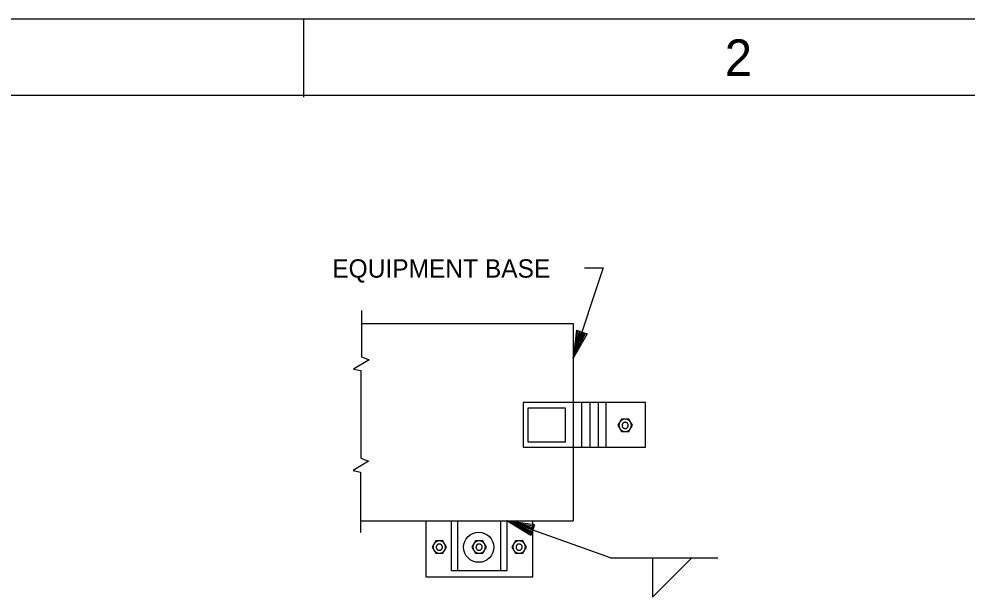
# Model space of a CAD drawing. Extents: x 9999.96 to 10005.26, y 9999.88 to 10002.38.
# Drawn here: x 10002.153 to 10002.67, y 10002.069 to 10002.385 of the extents above; entities that cross this region are included whole.
import ezdxf

# ---------------------------------------------------------------- set-up
doc = ezdxf.new("R2010")
doc.units = 0
doc.layers.add('Level 1', color=7, linetype='Continuous')
doc.layers.add('Level 2', color=7, linetype='Continuous')

msp = doc.modelspace()

# ---------------------------------------------------------------- linework, layer by layer
at = {"layer": 'Level 1'}
for p, q in [((9999.96033, 10002.38453), (10003.46033, 10002.38453)), ((10002.30795, 10002.38453), (10002.30795, 10002.34186)), ((10000.127, 10002.34286), (10003.41867, 10002.34286))]:
    msp.add_line(p, q, dxfattribs=at)
at = {"layer": 'Level 2'}
for p, q in [((10002.33947, 10002.21838), (10002.45502, 10002.21838)), ((10002.45502, 10002.21838), (10002.45502, 10002.17513)), ((10002.45681, 10002.21463), (10002.45491, 10002.1994)), ((10002.45491, 10002.1994), (10002.45754, 10002.21439)), ((10002.45491, 10002.1994), (10002.45835, 10002.21414)), ((10002.45491, 10002.1994), (10002.45898, 10002.21391)), ((10002.45965, 10002.2137), (10002.45491, 10002.1994)), ((10002.45491, 10002.1994), (10002.46036, 10002.21345)), ((10002.45491, 10002.1994), (10002.46107, 10002.21322)), ((10002.45491, 10002.1994), (10002.46175, 10002.21298)), ((10002.46253, 10002.21271), (10002.45491, 10002.1994)), ((10002.45681, 10002.21463), (10002.46253, 10002.21271)), ((10002.45488, 10002.17526), (10002.45488, 10002.15077)), ((10002.45942, 10002.17526), (10002.45942, 10002.15077)), ((10002.46395, 10002.17526), (10002.46395, 10002.15077)), ((10002.46863, 10002.17526), (10002.46863, 10002.15077)), ((10002.47274, 10002.17526), (10002.47274, 10002.15077)), ((10002.45502, 10002.15081), (10002.45502, 10002.11064)), ((10002.33921, 10002.11064), (10002.45502, 10002.11064)), ((10002.39183, 10002.11061), (10002.39183, 10002.08332)), ((10002.41539, 10002.11061), (10002.41539, 10002.08332)), ((10002.47527, 10002.09039), (10002.41874, 10002.11061)), ((10002.43293, 10002.10556), (10002.41874, 10002.11061)), ((10002.43189, 10002.1027), (10002.41874, 10002.11061)), ((10002.43393, 10002.10836), (10002.41874, 10002.11061)), ((10002.41874, 10002.11061), (10002.43243, 10002.10415)), ((10002.41874, 10002.11061), (10002.43341, 10002.10684)), ((10002.41874, 10002.11061), (10002.43218, 10002.10347)), ((10002.41874, 10002.11061), (10002.43267, 10002.10485)), ((10002.41874, 10002.11061), (10002.43316, 10002.10622)), ((10002.41874, 10002.11061), (10002.43367, 10002.10765)), ((10002.43393, 10002.10836), (10002.43189, 10002.1027)), ((10002.47527, 10002.09039), (10002.53378, 10002.09039)), ((10002.4982, 10002.09039), (10002.4982, 10002.06903)), ((10002.4982, 10002.06903), (10002.51955, 10002.09039))]:
    msp.add_line(p, q, dxfattribs=at)
for points in [[(10002.46114, 10002.24871), (10002.47133, 10002.24871), (10002.45491, 10002.1994)], [(10002.33948, 10002.22547), (10002.33948, 10002.20021), (10002.34369, 10002.19852), (10002.33526, 10002.19346), (10002.3392, 10002.19261), (10002.3392, 10002.16564)], [(10002.3392, 10002.16564), (10002.3392, 10002.14484), (10002.34341, 10002.14316), (10002.33498, 10002.13809), (10002.33892, 10002.13725), (10002.33892, 10002.10419)], [(10002.37467, 10002.11058), (10002.37467, 10002.08014), (10002.43301, 10002.08014), (10002.43301, 10002.11058)], [(10002.41874, 10002.11061), (10002.41874, 10002.08332), (10002.38857, 10002.08332), (10002.38857, 10002.11061)]]:
    msp.add_lwpolyline(points, dxfattribs=at)
for points in [[(10002.42777, 10002.17526), (10002.42777, 10002.15077), (10002.49436, 10002.15077), (10002.49436, 10002.17526)], [(10002.45055, 10002.17229), (10002.45055, 10002.15356), (10002.43034, 10002.15356), (10002.43034, 10002.17229)], [(10002.48726, 10002.16275), (10002.48527, 10002.16619), (10002.48131, 10002.16619), (10002.47933, 10002.16275), (10002.48131, 10002.15934), (10002.48527, 10002.15934)], [(10002.48665, 10002.16233), (10002.4867, 10002.16297), (10002.48665, 10002.16317), (10002.48663, 10002.1634), (10002.48659, 10002.1636), (10002.48652, 10002.16381), (10002.48646, 10002.164), (10002.48638, 10002.1642), (10002.48628, 10002.16439), (10002.48616, 10002.16458), (10002.48604, 10002.16474), (10002.48591, 10002.16492), (10002.48577, 10002.16507), (10002.48561, 10002.16522), (10002.48547, 10002.16538), (10002.48528, 10002.1655), (10002.48513, 10002.16563), (10002.48494, 10002.16574), (10002.48474, 10002.16582), (10002.48454, 10002.16591), (10002.48433, 10002.16598), (10002.48415, 10002.16605), (10002.48392, 10002.16608), (10002.48372, 10002.16611), (10002.4835, 10002.16615), (10002.48329, 10002.16615), (10002.48308, 10002.16615), (10002.48288, 10002.16611), (10002.48266, 10002.16608), (10002.48244, 10002.16605), (10002.48225, 10002.16598), (10002.48205, 10002.16591), (10002.48184, 10002.16582), (10002.48166, 10002.16574), (10002.48148, 10002.16563), (10002.48131, 10002.1655), (10002.48113, 10002.16538), (10002.48099, 10002.16522), (10002.48082, 10002.16507), (10002.48068, 10002.16492), (10002.48054, 10002.16474), (10002.48044, 10002.16458), (10002.48032, 10002.16439), (10002.48021, 10002.1642), (10002.48013, 10002.164), (10002.48007, 10002.16381), (10002.48, 10002.1636), (10002.47997, 10002.1634), (10002.47994, 10002.16317), (10002.47991, 10002.16297), (10002.47991, 10002.16275), (10002.47991, 10002.16255), (10002.47994, 10002.16233), (10002.47997, 10002.16211), (10002.48, 10002.16191), (10002.48007, 10002.16171), (10002.48013, 10002.16151), (10002.48021, 10002.16131), (10002.48032, 10002.1611), (10002.48044, 10002.16094), (10002.48054, 10002.16076), (10002.48068, 10002.16059), (10002.48082, 10002.16045), (10002.48099, 10002.16028), (10002.48113, 10002.16014), (10002.48131, 10002.16001), (10002.48148, 10002.1599), (10002.48166, 10002.15978), (10002.48184, 10002.15969), (10002.48205, 10002.15959), (10002.48225, 10002.15953), (10002.48244, 10002.15946), (10002.48266, 10002.15943), (10002.48288, 10002.15938), (10002.48308, 10002.15936), (10002.48329, 10002.15936), (10002.4835, 10002.15936), (10002.48372, 10002.15938), (10002.48392, 10002.15943), (10002.48415, 10002.15946), (10002.48433, 10002.15953), (10002.48454, 10002.15959), (10002.48474, 10002.15969), (10002.48494, 10002.15978), (10002.48513, 10002.1599), (10002.48528, 10002.16001), (10002.48547, 10002.16014), (10002.48561, 10002.16028), (10002.48577, 10002.16045), (10002.48591, 10002.16059), (10002.48604, 10002.16076), (10002.48616, 10002.16094), (10002.48628, 10002.1611), (10002.48638, 10002.16131), (10002.48646, 10002.16151), (10002.48652, 10002.16171), (10002.48659, 10002.16191), (10002.48663, 10002.16211)], [(10002.48498, 10002.16248), (10002.48499, 10002.16281), (10002.48498, 10002.16292), (10002.48495, 10002.16302), (10002.48494, 10002.16314), (10002.48491, 10002.16323), (10002.48488, 10002.16333), (10002.48483, 10002.16343), (10002.48479, 10002.16351), (10002.48472, 10002.16363), (10002.48467, 10002.16371), (10002.4846, 10002.16379), (10002.48453, 10002.16389), (10002.48446, 10002.16393), (10002.48438, 10002.16402), (10002.4843, 10002.16408), (10002.48422, 10002.16414), (10002.48411, 10002.1642), (10002.48401, 10002.16424), (10002.48391, 10002.16429), (10002.48382, 10002.16431), (10002.48372, 10002.16434), (10002.48363, 10002.16438), (10002.4835, 10002.16439), (10002.48341, 10002.1644), (10002.48329, 10002.1644), (10002.48319, 10002.1644), (10002.48307, 10002.16439), (10002.48298, 10002.16438), (10002.48285, 10002.16434), (10002.48275, 10002.16431), (10002.48266, 10002.16429), (10002.48257, 10002.16424), (10002.48247, 10002.1642), (10002.48239, 10002.16414), (10002.4823, 10002.16408), (10002.48219, 10002.16402), (10002.48214, 10002.16393), (10002.48205, 10002.16389), (10002.48198, 10002.16379), (10002.48192, 10002.16371), (10002.48184, 10002.16363), (10002.48181, 10002.16351), (10002.48175, 10002.16343), (10002.4817, 10002.16333), (10002.48168, 10002.16323), (10002.48164, 10002.16314), (10002.48161, 10002.16302), (10002.4816, 10002.16292), (10002.48158, 10002.16281), (10002.48158, 10002.16269), (10002.48158, 10002.16259), (10002.4816, 10002.16248), (10002.48161, 10002.1624), (10002.48164, 10002.16226), (10002.48168, 10002.16218), (10002.4817, 10002.16207), (10002.48175, 10002.16198), (10002.48181, 10002.16186), (10002.48184, 10002.16178), (10002.48192, 10002.16171), (10002.48198, 10002.16161), (10002.48205, 10002.16154), (10002.48214, 10002.16145), (10002.48219, 10002.16141), (10002.4823, 10002.16133), (10002.48239, 10002.16127), (10002.48247, 10002.16121), (10002.48257, 10002.16117), (10002.48266, 10002.1611), (10002.48275, 10002.16108), (10002.48285, 10002.16104), (10002.48298, 10002.16103), (10002.48307, 10002.16102), (10002.48319, 10002.161), (10002.48329, 10002.161), (10002.48341, 10002.161), (10002.4835, 10002.16102), (10002.48363, 10002.16103), (10002.48372, 10002.16104), (10002.48382, 10002.16108), (10002.48391, 10002.1611), (10002.48401, 10002.16117), (10002.48411, 10002.16121), (10002.48422, 10002.16127), (10002.4843, 10002.16133), (10002.48438, 10002.16141), (10002.48446, 10002.16145), (10002.48453, 10002.16154), (10002.4846, 10002.16161), (10002.48467, 10002.16171), (10002.48472, 10002.16178), (10002.48479, 10002.16186), (10002.48483, 10002.16198), (10002.48488, 10002.16207), (10002.48491, 10002.16218), (10002.48494, 10002.16226), (10002.48495, 10002.1624)], [(10002.38596, 10002.0963), (10002.38397, 10002.09974), (10002.38001, 10002.09974), (10002.37803, 10002.0963), (10002.38001, 10002.0929), (10002.38397, 10002.0929)], [(10002.38534, 10002.09589), (10002.3854, 10002.09652), (10002.38534, 10002.09672), (10002.38532, 10002.09695), (10002.38529, 10002.09716), (10002.38522, 10002.09736), (10002.38516, 10002.09755), (10002.38507, 10002.09775), (10002.38498, 10002.09794), (10002.38485, 10002.09814), (10002.38474, 10002.09829), (10002.3846, 10002.09847), (10002.38447, 10002.09863), (10002.38431, 10002.09877), (10002.38417, 10002.09893), (10002.38398, 10002.09905), (10002.38382, 10002.09918), (10002.38364, 10002.09929), (10002.38344, 10002.09938), (10002.38324, 10002.09946), (10002.38303, 10002.09953), (10002.38284, 10002.0996), (10002.38261, 10002.09964), (10002.38242, 10002.09967), (10002.3822, 10002.0997), (10002.38199, 10002.0997), (10002.38178, 10002.0997), (10002.38157, 10002.09967), (10002.38135, 10002.09964), (10002.38114, 10002.0996), (10002.38095, 10002.09953), (10002.38075, 10002.09946), (10002.38054, 10002.09938), (10002.38035, 10002.09929), (10002.38018, 10002.09918), (10002.38001, 10002.09905), (10002.37982, 10002.09893), (10002.37969, 10002.09877), (10002.37952, 10002.09863), (10002.37938, 10002.09847), (10002.37924, 10002.09829), (10002.37914, 10002.09814), (10002.37902, 10002.09794), (10002.37891, 10002.09775), (10002.37882, 10002.09755), (10002.37877, 10002.09736), (10002.3787, 10002.09716), (10002.37867, 10002.09695), (10002.37864, 10002.09672), (10002.3786, 10002.09652), (10002.3786, 10002.0963), (10002.3786, 10002.0961), (10002.37864, 10002.09589), (10002.37867, 10002.09567), (10002.3787, 10002.09546), (10002.37877, 10002.09526), (10002.37882, 10002.09506), (10002.37891, 10002.09486), (10002.37902, 10002.09466), (10002.37914, 10002.09449), (10002.37924, 10002.09431), (10002.37938, 10002.09415), (10002.37952, 10002.094), (10002.37969, 10002.09383), (10002.37982, 10002.09369), (10002.38001, 10002.09356), (10002.38018, 10002.09345), (10002.38035, 10002.09333), (10002.38054, 10002.09324), (10002.38075, 10002.09315), (10002.38095, 10002.09308), (10002.38114, 10002.09301), (10002.38135, 10002.09298), (10002.38157, 10002.09293), (10002.38178, 10002.09292), (10002.38199, 10002.09292), (10002.3822, 10002.09292), (10002.38242, 10002.09293), (10002.38261, 10002.09298), (10002.38284, 10002.09301), (10002.38303, 10002.09308), (10002.38324, 10002.09315), (10002.38344, 10002.09324), (10002.38364, 10002.09333), (10002.38382, 10002.09345), (10002.38398, 10002.09356), (10002.38417, 10002.09369), (10002.38431, 10002.09383), (10002.38447, 10002.094), (10002.3846, 10002.09415), (10002.38474, 10002.09431), (10002.38485, 10002.09449), (10002.38498, 10002.09466), (10002.38507, 10002.09486), (10002.38516, 10002.09506), (10002.38522, 10002.09526), (10002.38529, 10002.09546), (10002.38532, 10002.09567)], [(10002.38368, 10002.09603), (10002.38369, 10002.09636), (10002.38368, 10002.09647), (10002.38365, 10002.09657), (10002.38364, 10002.09669), (10002.3836, 10002.09678), (10002.38357, 10002.09689), (10002.38353, 10002.09698), (10002.38349, 10002.09706), (10002.38342, 10002.09718), (10002.38336, 10002.09726), (10002.3833, 10002.09734), (10002.38323, 10002.09744), (10002.38316, 10002.09748), (10002.38307, 10002.09757), (10002.383, 10002.09764), (10002.38292, 10002.09769), (10002.38281, 10002.09775), (10002.38271, 10002.09779), (10002.3826, 10002.09784), (10002.38252, 10002.09786), (10002.38242, 10002.0979), (10002.38232, 10002.09793), (10002.3822, 10002.09794), (10002.3821, 10002.09795), (10002.38199, 10002.09795), (10002.38189, 10002.09795), (10002.38177, 10002.09794), (10002.38168, 10002.09793), (10002.38155, 10002.0979), (10002.38145, 10002.09786), (10002.38135, 10002.09784), (10002.38127, 10002.09779), (10002.38117, 10002.09775), (10002.38108, 10002.09769), (10002.381, 10002.09764), (10002.38089, 10002.09757), (10002.38083, 10002.09748), (10002.38075, 10002.09744), (10002.38068, 10002.09734), (10002.38061, 10002.09726), (10002.38054, 10002.09718), (10002.38051, 10002.09706), (10002.38045, 10002.09698), (10002.3804, 10002.09689), (10002.38038, 10002.09678), (10002.38033, 10002.09669), (10002.38031, 10002.09657), (10002.3803, 10002.09647), (10002.38028, 10002.09636), (10002.38028, 10002.09624), (10002.38028, 10002.09615), (10002.3803, 10002.09603), (10002.38031, 10002.09595), (10002.38033, 10002.09581), (10002.38038, 10002.09573), (10002.3804, 10002.09563), (10002.38045, 10002.09553), (10002.38051, 10002.09542), (10002.38054, 10002.09533), (10002.38061, 10002.09526), (10002.38068, 10002.09517), (10002.38075, 10002.09509), (10002.38083, 10002.095), (10002.38089, 10002.09496), (10002.381, 10002.09489), (10002.38108, 10002.09482), (10002.38117, 10002.09476), (10002.38127, 10002.09472), (10002.38135, 10002.09466), (10002.38145, 10002.09464), (10002.38155, 10002.09459), (10002.38168, 10002.09458), (10002.38177, 10002.09457), (10002.38189, 10002.09455), (10002.38199, 10002.09455), (10002.3821, 10002.09455), (10002.3822, 10002.09457), (10002.38232, 10002.09458), (10002.38242, 10002.09459), (10002.38252, 10002.09464), (10002.3826, 10002.09466), (10002.38271, 10002.09472), (10002.38281, 10002.09476), (10002.38292, 10002.09482), (10002.383, 10002.09489), (10002.38307, 10002.09496), (10002.38316, 10002.095), (10002.38323, 10002.09509), (10002.3833, 10002.09517), (10002.38336, 10002.09526), (10002.38342, 10002.09533), (10002.38349, 10002.09542), (10002.38353, 10002.09553), (10002.38357, 10002.09563), (10002.3836, 10002.09573), (10002.38364, 10002.09581), (10002.38365, 10002.09595)], [(10002.40764, 10002.0963), (10002.40565, 10002.09974), (10002.40169, 10002.09974), (10002.39971, 10002.0963), (10002.40169, 10002.0929), (10002.40565, 10002.0929)], [(10002.40702, 10002.09589), (10002.40707, 10002.09652), (10002.40702, 10002.09672), (10002.407, 10002.09695), (10002.40697, 10002.09716), (10002.4069, 10002.09736), (10002.40683, 10002.09755), (10002.40675, 10002.09775), (10002.40666, 10002.09794), (10002.40653, 10002.09814), (10002.40642, 10002.09829), (10002.40628, 10002.09847), (10002.40615, 10002.09863), (10002.40599, 10002.09877), (10002.40584, 10002.09893), (10002.40566, 10002.09905), (10002.4055, 10002.09918), (10002.40531, 10002.09929), (10002.40511, 10002.09938), (10002.40492, 10002.09946), (10002.40471, 10002.09953), (10002.40452, 10002.0996), (10002.40429, 10002.09964), (10002.40409, 10002.09967), (10002.40388, 10002.0997), (10002.40367, 10002.0997), (10002.40346, 10002.0997), (10002.40325, 10002.09967), (10002.40303, 10002.09964), (10002.40281, 10002.0996), (10002.40263, 10002.09953), (10002.40243, 10002.09946), (10002.40222, 10002.09938), (10002.40203, 10002.09929), (10002.40185, 10002.09918), (10002.40169, 10002.09905), (10002.4015, 10002.09893), (10002.40136, 10002.09877), (10002.4012, 10002.09863), (10002.40105, 10002.09847), (10002.40092, 10002.09829), (10002.40081, 10002.09814), (10002.4007, 10002.09794), (10002.40058, 10002.09775), (10002.4005, 10002.09755), (10002.40045, 10002.09736), (10002.40038, 10002.09716), (10002.40034, 10002.09695), (10002.40031, 10002.09672), (10002.40028, 10002.09652), (10002.40028, 10002.0963), (10002.40028, 10002.0961), (10002.40031, 10002.09589), (10002.40034, 10002.09567), (10002.40038, 10002.09546), (10002.40045, 10002.09526), (10002.4005, 10002.09506), (10002.40058, 10002.09486), (10002.4007, 10002.09466), (10002.40081, 10002.09449), (10002.40092, 10002.09431), (10002.40105, 10002.09415), (10002.4012, 10002.094), (10002.40136, 10002.09383), (10002.4015, 10002.09369), (10002.40169, 10002.09356), (10002.40185, 10002.09345), (10002.40203, 10002.09333), (10002.40222, 10002.09324), (10002.40243, 10002.09315), (10002.40263, 10002.09308), (10002.40281, 10002.09301), (10002.40303, 10002.09298), (10002.40325, 10002.09293), (10002.40346, 10002.09292), (10002.40367, 10002.09292), (10002.40388, 10002.09292), (10002.40409, 10002.09293), (10002.40429, 10002.09298), (10002.40452, 10002.09301), (10002.40471, 10002.09308), (10002.40492, 10002.09315), (10002.40511, 10002.09324), (10002.40531, 10002.09333), (10002.4055, 10002.09345), (10002.40566, 10002.09356), (10002.40584, 10002.09369), (10002.40599, 10002.09383), (10002.40615, 10002.094), (10002.40628, 10002.09415), (10002.40642, 10002.09431), (10002.40653, 10002.09449), (10002.40666, 10002.09466), (10002.40675, 10002.09486), (10002.40683, 10002.09506), (10002.4069, 10002.09526), (10002.40697, 10002.09546), (10002.407, 10002.09567)], [(10002.40535, 10002.09603), (10002.40536, 10002.09636), (10002.40535, 10002.09647), (10002.40532, 10002.09657), (10002.40531, 10002.09669), (10002.40528, 10002.09678), (10002.40525, 10002.09689), (10002.40521, 10002.09698), (10002.40517, 10002.09706), (10002.40509, 10002.09718), (10002.40504, 10002.09726), (10002.40498, 10002.09734), (10002.40491, 10002.09744), (10002.40483, 10002.09748), (10002.40475, 10002.09757), (10002.40468, 10002.09764), (10002.40459, 10002.09769), (10002.40449, 10002.09775), (10002.40439, 10002.09779), (10002.40428, 10002.09784), (10002.4042, 10002.09786), (10002.40409, 10002.0979), (10002.404, 10002.09793), (10002.40388, 10002.09794), (10002.40378, 10002.09795), (10002.40367, 10002.09795), (10002.40356, 10002.09795), (10002.40345, 10002.09794), (10002.40335, 10002.09793), (10002.40323, 10002.0979), (10002.40313, 10002.09786), (10002.40303, 10002.09784), (10002.40295, 10002.09779), (10002.40284, 10002.09775), (10002.40276, 10002.09769), (10002.40268, 10002.09764), (10002.40256, 10002.09757), (10002.40251, 10002.09748), (10002.40243, 10002.09744), (10002.40235, 10002.09734), (10002.40229, 10002.09726), (10002.40222, 10002.09718), (10002.40219, 10002.09706), (10002.40213, 10002.09698), (10002.40207, 10002.09689), (10002.40205, 10002.09678), (10002.40201, 10002.09669), (10002.40199, 10002.09657), (10002.40198, 10002.09647), (10002.40196, 10002.09636), (10002.40196, 10002.09624), (10002.40196, 10002.09615), (10002.40198, 10002.09603), (10002.40199, 10002.09595), (10002.40201, 10002.09581), (10002.40205, 10002.09573), (10002.40207, 10002.09563), (10002.40213, 10002.09553), (10002.40219, 10002.09542), (10002.40222, 10002.09533), (10002.40229, 10002.09526), (10002.40235, 10002.09517), (10002.40243, 10002.09509), (10002.40251, 10002.095), (10002.40256, 10002.09496), (10002.40268, 10002.09489), (10002.40276, 10002.09482), (10002.40284, 10002.09476), (10002.40295, 10002.09472), (10002.40303, 10002.09466), (10002.40313, 10002.09464), (10002.40323, 10002.09459), (10002.40335, 10002.09458), (10002.40345, 10002.09457), (10002.40356, 10002.09455), (10002.40367, 10002.09455), (10002.40378, 10002.09455), (10002.40388, 10002.09457), (10002.404, 10002.09458), (10002.40409, 10002.09459), (10002.4042, 10002.09464), (10002.40428, 10002.09466), (10002.40439, 10002.09472), (10002.40449, 10002.09476), (10002.40459, 10002.09482), (10002.40468, 10002.09489), (10002.40475, 10002.09496), (10002.40483, 10002.095), (10002.40491, 10002.09509), (10002.40498, 10002.09517), (10002.40504, 10002.09526), (10002.40509, 10002.09533), (10002.40517, 10002.09542), (10002.40521, 10002.09553), (10002.40525, 10002.09563), (10002.40528, 10002.09573), (10002.40531, 10002.09581), (10002.40532, 10002.09595)], [(10002.42946, 10002.0963), (10002.42747, 10002.09974), (10002.42351, 10002.09974), (10002.42153, 10002.0963), (10002.42351, 10002.0929), (10002.42747, 10002.0929)], [(10002.42884, 10002.09589), (10002.4289, 10002.09652), (10002.42884, 10002.09672), (10002.42882, 10002.09695), (10002.42879, 10002.09716), (10002.42872, 10002.09736), (10002.42866, 10002.09755), (10002.42857, 10002.09775), (10002.42848, 10002.09794), (10002.42835, 10002.09814), (10002.42824, 10002.09829), (10002.4281, 10002.09847), (10002.42797, 10002.09863), (10002.42781, 10002.09877), (10002.42767, 10002.09893), (10002.42748, 10002.09905), (10002.42732, 10002.09918), (10002.42714, 10002.09929), (10002.42694, 10002.09938), (10002.42674, 10002.09946), (10002.42653, 10002.09953), (10002.42634, 10002.0996), (10002.42611, 10002.09964), (10002.42592, 10002.09967), (10002.4257, 10002.0997), (10002.42549, 10002.0997), (10002.42528, 10002.0997), (10002.42507, 10002.09967), (10002.42485, 10002.09964), (10002.42464, 10002.0996), (10002.42445, 10002.09953), (10002.42425, 10002.09946), (10002.42404, 10002.09938), (10002.42385, 10002.09929), (10002.42368, 10002.09918), (10002.42351, 10002.09905), (10002.42332, 10002.09893), (10002.42319, 10002.09877), (10002.42302, 10002.09863), (10002.42288, 10002.09847), (10002.42274, 10002.09829), (10002.42264, 10002.09814), (10002.42252, 10002.09794), (10002.42241, 10002.09775), (10002.42232, 10002.09755), (10002.42227, 10002.09736), (10002.4222, 10002.09716), (10002.42217, 10002.09695), (10002.42214, 10002.09672), (10002.4221, 10002.09652), (10002.4221, 10002.0963), (10002.4221, 10002.0961), (10002.42214, 10002.09589), (10002.42217, 10002.09567), (10002.4222, 10002.09546), (10002.42227, 10002.09526), (10002.42232, 10002.09506), (10002.42241, 10002.09486), (10002.42252, 10002.09466), (10002.42264, 10002.09449), (10002.42274, 10002.09431), (10002.42288, 10002.09415), (10002.42302, 10002.094), (10002.42319, 10002.09383), (10002.42332, 10002.09369), (10002.42351, 10002.09356), (10002.42368, 10002.09345), (10002.42385, 10002.09333), (10002.42404, 10002.09324), (10002.42425, 10002.09315), (10002.42445, 10002.09308), (10002.42464, 10002.09301), (10002.42485, 10002.09298), (10002.42507, 10002.09293), (10002.42528, 10002.09292), (10002.42549, 10002.09292), (10002.4257, 10002.09292), (10002.42592, 10002.09293), (10002.42611, 10002.09298), (10002.42634, 10002.09301), (10002.42653, 10002.09308), (10002.42674, 10002.09315), (10002.42694, 10002.09324), (10002.42714, 10002.09333), (10002.42732, 10002.09345), (10002.42748, 10002.09356), (10002.42767, 10002.09369), (10002.42781, 10002.09383), (10002.42797, 10002.094), (10002.4281, 10002.09415), (10002.42824, 10002.09431), (10002.42835, 10002.09449), (10002.42848, 10002.09466), (10002.42857, 10002.09486), (10002.42866, 10002.09506), (10002.42872, 10002.09526), (10002.42879, 10002.09546), (10002.42882, 10002.09567)], [(10002.42718, 10002.09603), (10002.42719, 10002.09636), (10002.42718, 10002.09647), (10002.42715, 10002.09657), (10002.42714, 10002.09669), (10002.4271, 10002.09678), (10002.42707, 10002.09689), (10002.42703, 10002.09698), (10002.42699, 10002.09706), (10002.42692, 10002.09718), (10002.42686, 10002.09726), (10002.4268, 10002.09734), (10002.42673, 10002.09744), (10002.42666, 10002.09748), (10002.42657, 10002.09757), (10002.4265, 10002.09764), (10002.42642, 10002.09769), (10002.42631, 10002.09775), (10002.42621, 10002.09779), (10002.4261, 10002.09784), (10002.42602, 10002.09786), (10002.42592, 10002.0979), (10002.42582, 10002.09793), (10002.4257, 10002.09794), (10002.4256, 10002.09795), (10002.42549, 10002.09795), (10002.42539, 10002.09795), (10002.42527, 10002.09794), (10002.42518, 10002.09793), (10002.42505, 10002.0979), (10002.42495, 10002.09786), (10002.42485, 10002.09784), (10002.42477, 10002.09779), (10002.42467, 10002.09775), (10002.42458, 10002.09769), (10002.4245, 10002.09764), (10002.42439, 10002.09757), (10002.42433, 10002.09748), (10002.42425, 10002.09744), (10002.42418, 10002.09734), (10002.42411, 10002.09726), (10002.42404, 10002.09718), (10002.42401, 10002.09706), (10002.42395, 10002.09698), (10002.4239, 10002.09689), (10002.42388, 10002.09678), (10002.42383, 10002.09669), (10002.42381, 10002.09657), (10002.4238, 10002.09647), (10002.42378, 10002.09636), (10002.42378, 10002.09624), (10002.42378, 10002.09615), (10002.4238, 10002.09603), (10002.42381, 10002.09595), (10002.42383, 10002.09581), (10002.42388, 10002.09573), (10002.4239, 10002.09563), (10002.42395, 10002.09553), (10002.42401, 10002.09542), (10002.42404, 10002.09533), (10002.42411, 10002.09526), (10002.42418, 10002.09517), (10002.42425, 10002.09509), (10002.42433, 10002.095), (10002.42439, 10002.09496), (10002.4245, 10002.09489), (10002.42458, 10002.09482), (10002.42467, 10002.09476), (10002.42477, 10002.09472), (10002.42485, 10002.09466), (10002.42495, 10002.09464), (10002.42505, 10002.09459), (10002.42518, 10002.09458), (10002.42527, 10002.09457), (10002.42539, 10002.09455), (10002.42549, 10002.09455), (10002.4256, 10002.09455), (10002.4257, 10002.09457), (10002.42582, 10002.09458), (10002.42592, 10002.09459), (10002.42602, 10002.09464), (10002.4261, 10002.09466), (10002.42621, 10002.09472), (10002.42631, 10002.09476), (10002.42642, 10002.09482), (10002.4265, 10002.09489), (10002.42657, 10002.09496), (10002.42666, 10002.095), (10002.42673, 10002.09509), (10002.4268, 10002.09517), (10002.42686, 10002.09526), (10002.42692, 10002.09533), (10002.42699, 10002.09542), (10002.42703, 10002.09553), (10002.42707, 10002.09563), (10002.4271, 10002.09573), (10002.42714, 10002.09581), (10002.42715, 10002.09595)]]:
    msp.add_lwpolyline(points, close=True, dxfattribs=at)
msp.add_circle((10002.40345, 10002.09622), 0.00823, dxfattribs=at)

# ---------------------------------------------------------------- texts
at = {"layer": 'Level 1'}
msp.add_text('2', height=0.02, dxfattribs=at).set_placement((10002.53758, 10002.35336))
at = {"layer": 'Level 2'}
msp.add_text('EQUIPMENT BASE', height=0.01, dxfattribs=at).set_placement((10002.3236, 10002.24335))

doc.saveas('drawing.dxf')
